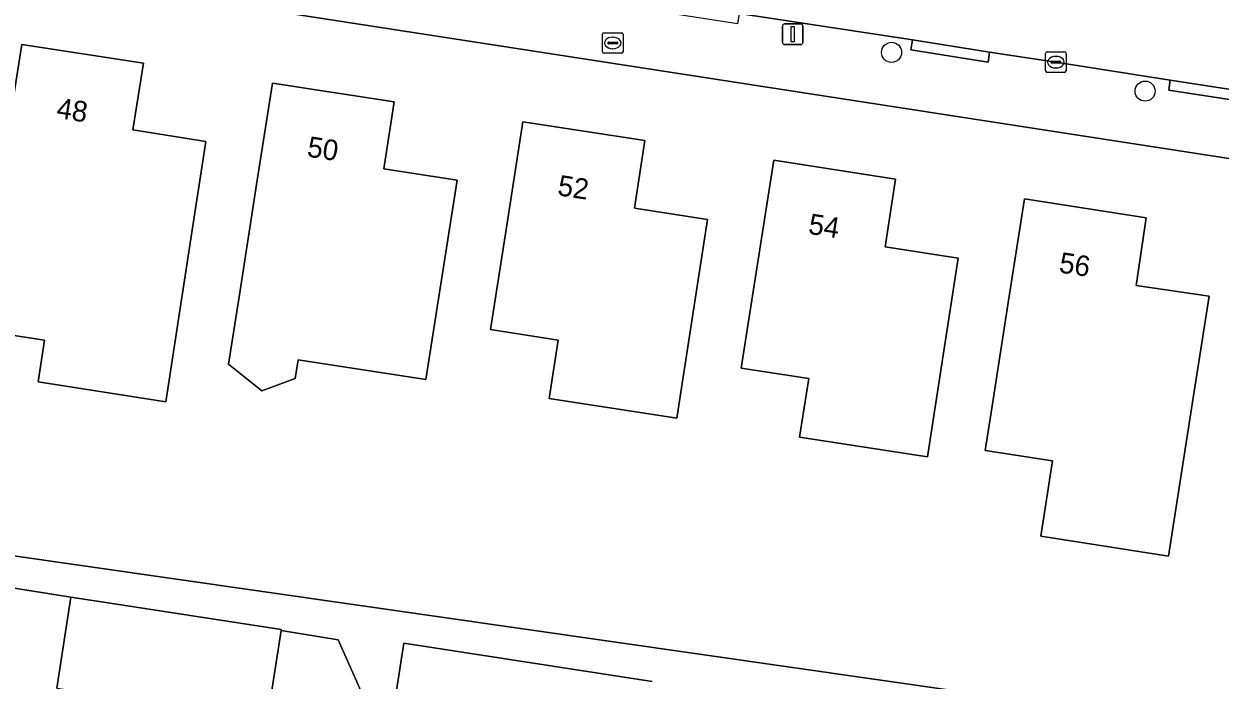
# Model space of a CAD drawing. Extents: x 161483 to 162250, y 379484 to 380833.
# Drawn here: x 161829.9 to 161888.1, y 380603.9 to 380635.8 of the extents above; entities that cross this region are included whole.
import ezdxf

# ---------------------------------------------------------------- set-up
doc = ezdxf.new("R2010")
doc.units = 0
for name, color, linetype in [('IMGEO_Boom', 7, 'Continuous'), ('IMGEO_Brandkraan', 7, 'Continuous'), ('IMGEO_Erf', 7, 'Continuous'), ('IMGEO_Kolk', 7, 'Continuous'), ('IMGEO_Lichtmast', 7, 'Continuous'), ('IMGEO_Pand', 7, 'Continuous'), ('IMGEO_Pand_nummerreeks', 7, 'Continuous'), ('IMGEO_Rijbaan_lokaal_open', 7, 'Continuous'), ('IMGEO_Voetpad_open', 7, 'Continuous')]:
    doc.layers.add(name, color=color, linetype=linetype)

msp = doc.modelspace()

# ---------------------------------------------------------------- linework, layer by layer
at = {"layer": 'IMGEO_Boom'}
for centre in [(161872.09, 380634.456), (161884.422, 380632.568)]:
    msp.add_circle(centre, 0.489, dxfattribs=at)
at = {"layer": 'IMGEO_Brandkraan'}
for p, q in [((161858.025, 380634.487), (161858.025, 380635.339)), ((161858.1, 380635.413), (161858.952, 380635.413)), ((161858.513, 380635.193), (161858.538, 380635.193)), ((161859.026, 380635.339), (161859.026, 380634.487)), ((161858.284, 380634.907), (161858.284, 380634.919)), ((161858.722, 380634.87), (161858.324, 380634.87)), ((161858.327, 380634.956), (161858.725, 380634.956)), ((161858.536, 380634.633), (161858.511, 380634.633)), ((161858.768, 380634.919), (161858.768, 380634.907)), ((161858.952, 380634.413), (161858.1, 380634.413))]:
    msp.add_line(p, q, dxfattribs=at)
for points in [[(161858.025, 380634.487), (161858.025, 380635.339)], [(161858.1, 380635.413), (161858.952, 380635.413)], [(161859.026, 380635.339), (161859.026, 380634.487)], [(161858.952, 380634.413), (161858.1, 380634.413)]]:
    msp.add_lwpolyline(points, dxfattribs=at)
for centre, radius, start, end in [((161858.102, 380635.337), 0.0765, 91.55205, 178.44795), ((161858.102, 380635.337), 0.0765, 91.55205, 178.44795), ((161858.95, 380635.337), 0.0765, 1.55205, 88.44795), ((161858.95, 380635.337), 0.0765, 1.55205, 88.44795), ((161858.102, 380634.489), 0.0765, 181.55205, 268.44795), ((161858.102, 380634.489), 0.0765, 181.55205, 268.44795), ((161858.324, 380634.916), 0.0403, 85.87752, 175.75265), ((161858.321, 380634.906), 0.0366, 178.93798, 274.71019), ((161858.725, 380634.913), 0.043, 264.86636, 352.45326), ((161858.729, 380634.918), 0.0386, 1.73085, 96.63898), ((161858.95, 380634.489), 0.0765, 271.55205, 358.44795), ((161858.95, 380634.489), 0.0765, 271.55205, 358.44795)]:
    msp.add_arc(centre, radius, start, end, dxfattribs=at)
for centre, major_axis, ratio, start_param, end_param in [((161858.512, 380634.913), (-0.387, 0.002), 0.722429, 4.712389, 7.853982), ((161858.537, 380634.913), (-0.39, 0.002), 0.717154, 1.570796, 4.712389)]:
    msp.add_ellipse(centre, major_axis=major_axis, ratio=ratio, start_param=start_param, end_param=end_param, dxfattribs=at)
at = {"layer": 'IMGEO_Erf'}
for points in [[(161925.898, 380623.516), (161823.912, 380639.282), (161780.025, 380646.103), (161736.717, 380652.782), (161731.74, 380653.484)], [(161750.43, 380622.432), (161754.893, 380621.765), (161759.356, 380621.098), (161763.819, 380620.431), (161768.779, 380619.69), (161768.624, 380618.651), (161798.865, 380614.315), (161798.885, 380614.516), (161803.054, 380614.092), (161803.016, 380613.72), (161879.814, 380602.708)], [(161831.481, 380603.508), (161832.16, 380607.936), (161827.864, 380608.608)], [(161846.266, 380603.381), (161845.162, 380605.856), (161842.385, 380606.316), (161841.714, 380601.939)], [(161860.44, 380603.822), (161848.361, 380605.693), (161844.465, 380580.545)]]:
    msp.add_lwpolyline(points, dxfattribs=at)
for points in [[(161830.564, 380618.414), (161830.878, 380620.439), (161826.847, 380621.064), (161827.438, 380624.873), (161828.206, 380624.754), (161829.004, 380629.9), (161829.77, 380634.84), (161835.7, 380633.93), (161835.178, 380630.68), (161838.733, 380630.109), (161837.972, 380625.168), (161836.784, 380617.449)], [(161849.439, 380618.528), (161843.216, 380619.487), (161843.075, 380618.581), (161841.45, 380617.984), (161839.833, 380619.278), (161840.393, 380622.863), (161841.198, 380628.02), (161841.97, 380632.96), (161847.89, 380632.05), (161847.381, 380628.781), (161850.948, 380628.226), (161850.179, 380623.286)], [(161855.425, 380617.606), (161855.867, 380620.453), (161852.584, 380620.962), (161853.387, 380626.139), (161854.153, 380631.079), (161860.089, 380630.164), (161859.581, 380626.87), (161863.141, 380626.321), (161862.378, 380621.38), (161861.648, 380616.647)], [(161864.778, 380619.087), (161865.587, 380624.261), (161866.36, 380629.2), (161872.278, 380628.286), (161871.77, 380624.992), (161875.33, 380624.443), (161874.567, 380619.502), (161873.837, 380614.769), (161867.614, 380615.728), (161868.059, 380618.574)], [(161876.976, 380617.233), (161877.78, 380622.379), (161878.551, 380627.319), (161884.477, 380626.406), (161883.983, 380623.114), (161887.542, 380622.58), (161886.768, 380617.641), (161885.56, 380609.931), (161879.344, 380610.901), (161879.917, 380614.567), (161876.639, 380615.08)]]:
    msp.add_lwpolyline(points, close=True, dxfattribs=at)
at = {"layer": 'IMGEO_Kolk'}
for p, q in [((161879.58, 380633.553), (161879.58, 380634.405)), ((161879.655, 380634.479), (161880.507, 380634.479)), ((161879.839, 380633.973), (161879.839, 380633.985)), ((161880.277, 380633.936), (161879.879, 380633.936)), ((161879.882, 380634.022), (161880.28, 380634.022)), ((161880.068, 380634.259), (161880.093, 380634.259)), ((161880.323, 380633.985), (161880.323, 380633.973)), ((161880.581, 380634.405), (161880.581, 380633.553)), ((161880.507, 380633.479), (161879.655, 380633.479)), ((161880.091, 380633.699), (161880.066, 380633.699))]:
    msp.add_line(p, q, dxfattribs=at)
for points in [[(161879.58, 380633.553), (161879.58, 380634.405)], [(161879.655, 380634.479), (161880.507, 380634.479)], [(161880.581, 380634.405), (161880.581, 380633.553)], [(161880.507, 380633.479), (161879.655, 380633.479)]]:
    msp.add_lwpolyline(points, dxfattribs=at)
for centre, radius, start, end in [((161879.657, 380634.403), 0.0765, 91.55205, 178.44795), ((161879.657, 380634.403), 0.0765, 91.55205, 178.44795), ((161879.879, 380633.982), 0.0403, 85.87752, 175.75265), ((161879.876, 380633.972), 0.0366, 178.93798, 274.71019), ((161880.28, 380633.979), 0.043, 264.86636, 352.45326), ((161880.284, 380633.984), 0.0386, 1.73085, 96.63898), ((161880.505, 380634.403), 0.0765, 1.55205, 88.44795), ((161880.505, 380634.403), 0.0765, 1.55205, 88.44795), ((161879.657, 380633.555), 0.0765, 181.55205, 268.44795), ((161879.657, 380633.555), 0.0765, 181.55205, 268.44795), ((161880.505, 380633.555), 0.0765, 271.55205, 358.44795), ((161880.505, 380633.555), 0.0765, 271.55205, 358.44795)]:
    msp.add_arc(centre, radius, start, end, dxfattribs=at)
for centre, major_axis, ratio, start_param, end_param in [((161880.067, 380633.979), (-0.387, 0.002), 0.722429, 4.712389, 7.853982), ((161880.092, 380633.979), (-0.39, 0.002), 0.717154, 1.570796, 4.712389)]:
    msp.add_ellipse(centre, major_axis=major_axis, ratio=ratio, start_param=start_param, end_param=end_param, dxfattribs=at)
at = {"layer": 'IMGEO_Lichtmast'}
for p, q in [((161866.783, 380634.936), (161866.783, 380635.736)), ((161866.783, 380635.736), (161866.783, 380634.936)), ((161866.883, 380635.836), (161867.673, 380635.836)), ((161867.673, 380635.836), (161866.883, 380635.836)), ((161867.773, 380635.736), (161867.773, 380634.936)), ((161867.773, 380634.936), (161867.773, 380635.736)), ((161867.673, 380634.836), (161866.883, 380634.836)), ((161866.883, 380634.836), (161867.673, 380634.836))]:
    msp.add_line(p, q, dxfattribs=at)
msp.add_lwpolyline([(161867.203, 380635.711), (161867.353, 380635.711), (161867.353, 380634.961), (161867.203, 380634.961), (161867.203, 380635.711)], dxfattribs=at)
for centre, start, end in [((161866.883, 380635.736), 90, 180), ((161866.883, 380635.736), 90, 180), ((161867.673, 380635.736), 0, 90), ((161867.673, 380635.736), 360, 90), ((161866.883, 380634.936), 180, 270), ((161866.883, 380634.936), 180, 270), ((161867.673, 380634.936), 270, 0), ((161867.673, 380634.936), 270, 0)]:
    msp.add_arc(centre, 0.1, start, end, dxfattribs=at)
at = {"layer": 'IMGEO_Pand'}
for points in [[(161830.878, 380620.439), (161830.564, 380618.414), (161836.784, 380617.449), (161837.972, 380625.168), (161838.733, 380630.109), (161835.178, 380630.68), (161835.7, 380633.93), (161829.77, 380634.84), (161829.004, 380629.9), (161828.206, 380624.754), (161827.438, 380624.873), (161826.847, 380621.064)], [(161841.198, 380628.02), (161840.393, 380622.863), (161839.833, 380619.278), (161841.45, 380617.984), (161843.075, 380618.581), (161843.216, 380619.487), (161849.439, 380618.528), (161850.179, 380623.286), (161850.948, 380628.226), (161847.381, 380628.781), (161847.89, 380632.05), (161841.97, 380632.96)], [(161853.387, 380626.139), (161852.584, 380620.962), (161855.867, 380620.453), (161855.425, 380617.606), (161861.648, 380616.647), (161862.378, 380621.38), (161863.141, 380626.321), (161859.581, 380626.87), (161860.089, 380630.164), (161854.153, 380631.079)], [(161865.587, 380624.261), (161864.778, 380619.087), (161868.059, 380618.574), (161867.614, 380615.728), (161873.837, 380614.769), (161874.567, 380619.502), (161875.33, 380624.443), (161871.77, 380624.992), (161872.278, 380628.286), (161866.36, 380629.2)], [(161876.976, 380617.233), (161876.639, 380615.08), (161879.917, 380614.567), (161879.344, 380610.901), (161885.56, 380609.931), (161886.768, 380617.641), (161887.542, 380622.58), (161883.983, 380623.114), (161884.477, 380626.406), (161878.551, 380627.319), (161877.78, 380622.379)], [(161842.385, 380606.316), (161842.393, 380606.367), (161834.286, 380607.61), (161832.16, 380607.936), (161831.481, 380603.508), (161833.607, 380603.182), (161841.714, 380601.939)]]:
    msp.add_lwpolyline(points, close=True, dxfattribs=at)
at = {"layer": 'IMGEO_Rijbaan_lokaal_open'}
msp.add_lwpolyline([(161828.567, 380641.917), (161836.508, 380640.681), (161840.209, 380640.087), (161842.462, 380639.696), (161848.844, 380638.801), (161852.574, 380638.203), (161860.998, 380636.913), (161864.674, 380636.339), (161873.104, 380635.067), (161876.861, 380634.467), (161880.077, 380633.98), (161885.647, 380633.107), (161889.34, 380632.533), (161891.34, 380632.201), (161895.056, 380631.647), (161898.375, 380631.13), (161906.524, 380629.872), (161912.467, 380628.951), (161919.648, 380627.838), (161923.889, 380627.212), (161928.578, 380626.472)], dxfattribs=at)
at = {"layer": 'IMGEO_Voetpad_open'}
for points in [[(161807.605, 380805.299), (161802.298, 380806.133), (161797.296, 380773.35), (161796.862, 380770.298), (161796.426, 380767.228), (161798.606, 380766.939), (161795.986, 380750), (161793.024, 380730.851), (161790.225, 380712.603), (161787.978, 380697.958), (161781.385, 380654.948), (161780.025, 380646.103), (161823.912, 380639.282), (161925.898, 380623.516)], [(161889.264, 380632.039), (161885.571, 380632.613), (161885.647, 380633.107), (161880.077, 380633.98), (161876.861, 380634.467), (161876.783, 380633.974), (161873.026, 380634.574), (161873.104, 380635.067), (161864.674, 380636.339), (161864.597, 380635.845), (161860.921, 380636.419), (161860.998, 380636.913), (161852.574, 380638.203), (161852.495, 380637.71), (161848.765, 380638.308), (161848.844, 380638.801), (161842.462, 380639.696), (161840.209, 380640.087), (161840.13, 380639.594), (161836.429, 380640.188), (161836.508, 380640.681), (161828.567, 380641.917)], [(161879.814, 380602.708), (161803.016, 380613.72), (161802.871, 380612.3), (161814.172, 380610.628), (161815.364, 380610.507), (161815.359, 380610.453), (161823.099, 380609.308), (161823.592, 380609.237), (161823.596, 380609.262), (161825.73, 380608.935), (161826.133, 380608.873), (161827.864, 380608.608), (161832.16, 380607.936), (161834.286, 380607.61), (161842.393, 380606.367), (161842.385, 380606.316), (161845.162, 380605.856), (161846.266, 380603.381)], [(161844.465, 380580.545), (161848.361, 380605.693), (161860.44, 380603.822)]]:
    msp.add_lwpolyline(points, dxfattribs=at)
for points in [[(161876.861, 380634.467), (161873.104, 380635.067), (161873.026, 380634.574), (161876.783, 380633.974)], [(161889.34, 380632.533), (161885.647, 380633.107), (161885.571, 380632.613), (161889.264, 380632.039)]]:
    msp.add_lwpolyline(points, close=True, dxfattribs=at)

# ---------------------------------------------------------------- texts
at = {"layer": 'IMGEO_Pand_nummerreeks'}
for s, rotation, p in [('48', 351.27562, (161831.423, 380631.268)), ('50', 351.26111, (161843.617, 380629.388)), ('52', 351.23716, (161855.801, 380627.505)), ('54', 351.22037, (161868.001, 380625.628)), ('56', 351.23948, (161880.197, 380623.747))]:
    msp.add_text(s, height=1, rotation=rotation, dxfattribs=at).set_placement(p)

doc.saveas('drawing.dxf')
